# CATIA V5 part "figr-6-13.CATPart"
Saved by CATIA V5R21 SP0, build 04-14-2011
Part number: Part1
Bounding box of the stored display mesh (mm): x -25 to 25, y -75 to 75, z 0 to 20
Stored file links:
  D:\CATIA V5R21 E-RESOURCES\CATIA-V5R21\catia-v5r21-prt\c06-catia-v5r21-prt\c06-catia-v5r21-figr-6-13.CATPart
  C:\Program Files\Dassault Systemes\B13\intel_a\reffiles\standard\MetricThinPitch.txt
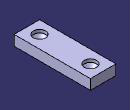
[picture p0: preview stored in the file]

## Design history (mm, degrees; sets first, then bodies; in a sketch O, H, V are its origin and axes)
Body1 (main body)
  Sketch1 on xy-plane, origin (0, 0, 0), H (1, 0, 0), V (0, 1, 0)
    line L1 (-25, 75) -> (25, 75)
    line L2 (25, 75) -> (25, -75)
    line L3 (25, -75) -> (-25, -75)
    line L4 (-25, -75) -> (-25, 75)
    axis line L5 (25, -75) -> (-25, 75)
    length L2 = 150
    length L3 = 50
    horizontal: L1 H, L3 H
    vertical: L2 V, L4 V
    midpoint: O L5
  Pad1: profile Sketch1, direction (0, 0, 1), length 20
  Sketch2 on face of Pad1, origin (-8.6664, -28.8348, 20), H (1, 0, 0), V (0, 1, 0)
    point P1 (8.6664, -21.1652)
    reference projected line E1 (-16.3336, -46.1652) -> (33.6664, -46.1652) from edge [face of Pad1 | face of Pad1]
    reference projected line E2 (-16.3336, 103.8348) -> (-16.3336, -46.1652) from edge [face of Pad1 | face of Pad1]
    distance P1 E1 = 25
    distance P1 E2 = 25
  Hole1: placed by Sketch2, at (0, -50, 20) direction (0, 0, -1), diameter 10.647, through (limit type 3), type CounterDrilledType, Diameter 10.647, DiameterThread 12, Pas 1.25, Profile a sketch, Sketch Sketch2, ThreadDepth 10, ThreadDescription "M12", Angle 90, Depth 6, Diameter 24
  Sketch3 on face of Pad1, origin (3.6925, 50.8892, 20), H (1, 0, 0), V (0, 1, 0)
    point P1 (-3.6925, -0.8892)
    reference projected line E1 (-28.6925, 24.1108) -> (-28.6925, -125.8892) from edge [face of Pad1 | face of Pad1]
    reference projected line E2 (21.3075, 24.1108) -> (-28.6925, 24.1108) from edge [face of Pad1 | face of Pad1]
    distance P1 E1 = 25
    distance E2 P1 = 25
  Hole2: placed by Sketch3, at (0, 50, 20) direction (0, 0, -1), diameter 10.647, through (limit type 3), type CounterDrilledType, Diameter 10.647, DiameterThread 11.7117, Pas 1, Profile a sketch, Sketch Sketch3, ThreadDepth 10, Angle 90, Depth 6, Diameter 24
